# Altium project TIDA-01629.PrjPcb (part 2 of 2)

## Sheet TIDA-01629_Encoder.SchDoc
size 431 x 279 mm; Date: Not shown in title block; ApprovedBy: Not shown in title block; CheckedBy: Not shown in title block; Author: Not shown in title block; CompanyName: Not shown in title block; Engineer: Not shown in title block; Organization: Not shown in title block; Address1: Not shown in title block; Address2: Not shown in title block; Address3: Not shown in title block; Address4: Not shown in title block; DocumentNumber: 1; Revision: Use project parameter SCH_Rev; SheetNumber: 2; SheetTotal: 3; PageSetup: Record=PageOptions¦CenterHorizontal=True¦CenterVertical=True¦PrintScale=1.00¦XCorrection=1.00¦YCorrection=1.00¦PrintKind=0¦BorderSize=5000000¦LeftOffset=0¦BottomOffset=0¦Orientation=2¦PaperLength=1000¦PaperWidth=1000¦Scale=100¦PaperSource=15¦PrintQuality=600¦MediaType=1¦DitherType=10¦PaperKind=Letter¦PrintScaleMode=1
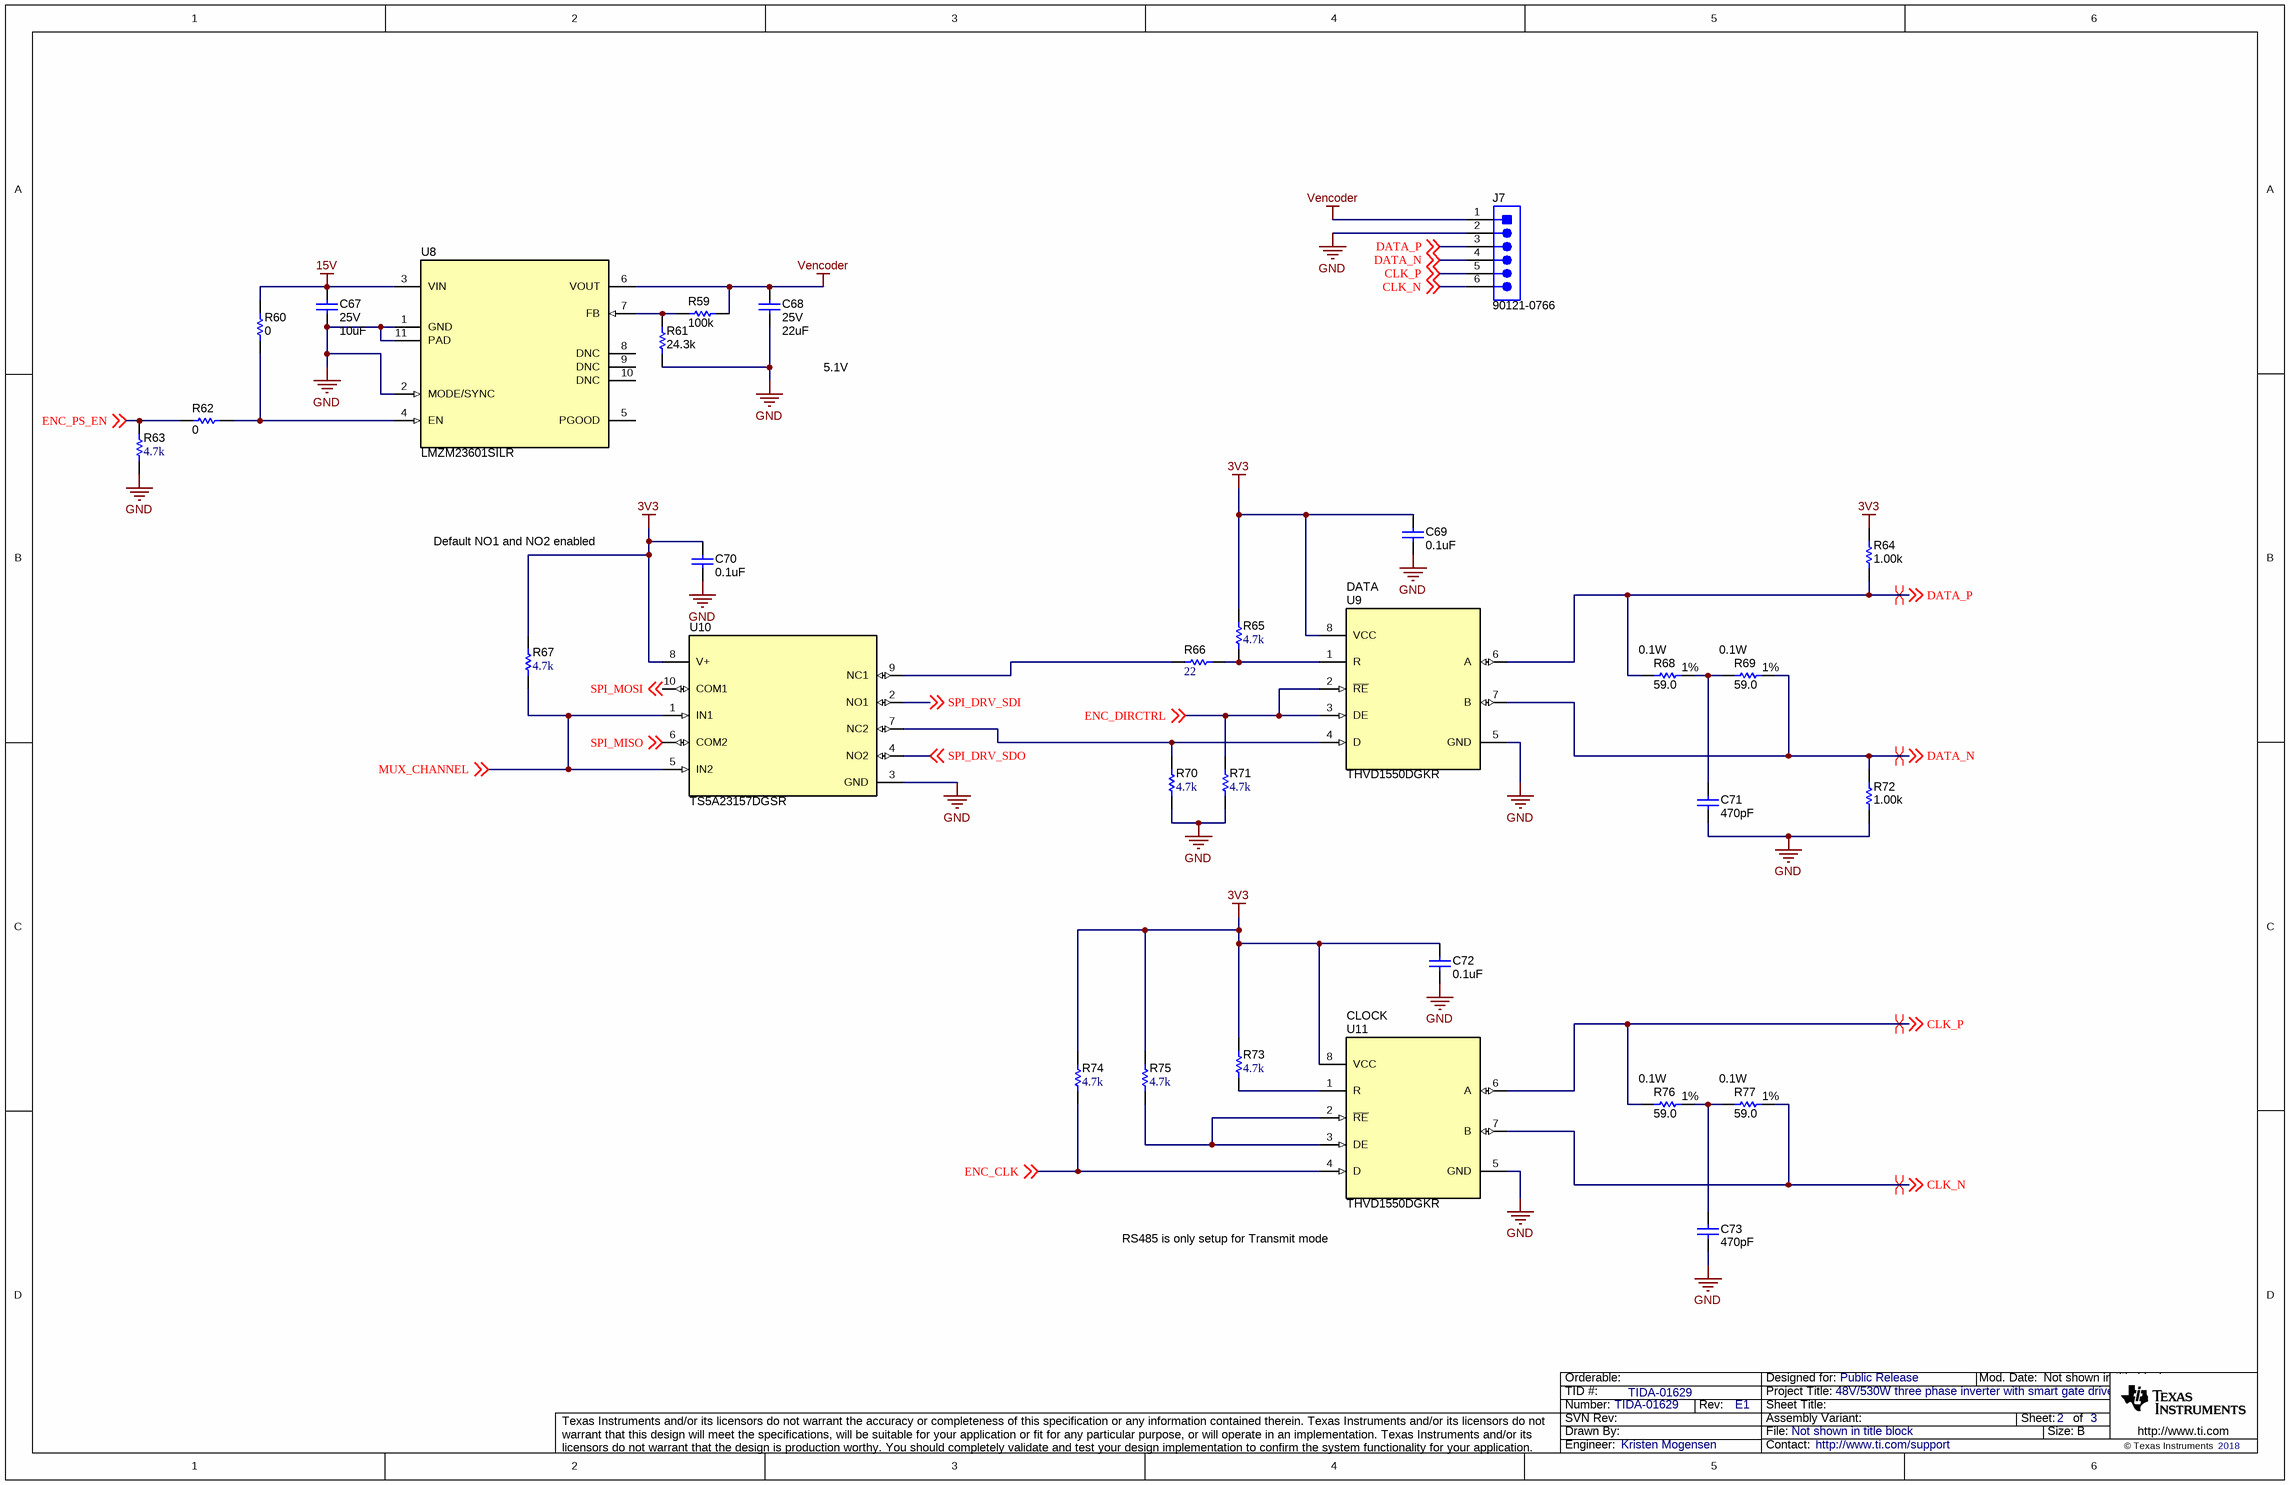
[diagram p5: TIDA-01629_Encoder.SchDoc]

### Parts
C67  VDC_V: 25V  ValueDisplayed: 10uF  [0805_HV]  (hidden comment: GRM21BZ71E106KE15L)
C68  VDC_V: 25V  ValueDisplayed: 22uF  [1210_270]  (hidden comment: GRM32ER71E226KE15L)
C69  ValueDisplayed: 0.1uF  [0402S]  (hidden comment: Capacitor)
C70  ValueDisplayed: 0.1uF  [0402S]  (hidden comment: Capacitor)
C71  ValueDisplayed: 470pF  [0603S]  (hidden comment: Capacitor)
C72  ValueDisplayed: 0.1uF  [0402S]  (hidden comment: Capacitor)
C73  ValueDisplayed: 470pF  [0603S]  (hidden comment: Capacitor)
J7  90121-0766  [Molex_90121-0766]
R59  ValueDisplayed: 100k  [0402]  (hidden comment: CRCW0402100KFKED)
R60  ValueDisplayed: 0  [0402S]  (hidden comment: Resistor)
R61  ValueDisplayed: 24.3k  [0402]  (hidden comment: CRCW040224K3FKED)
R62  ValueDisplayed: 0  [0402S]  (hidden comment: Resistor)
R63  ValueDisplayed: 4.7k  [0402S]  (hidden comment: CRCW04024K70JNED)
R64  ValueDisplayed: 1.00k  [0603L]  (hidden comment: CRCW06031K00FKEA)
R65  ValueDisplayed: 4.7k  [0402S]  (hidden comment: CRCW04024K70JNED)
R66  ValueDisplayed: 22  [0402S]  (hidden comment: CRCW040222R0JNED)
R67  ValueDisplayed: 4.7k  [0402S]  (hidden comment: CRCW04024K70JNED)
R68  ValueDisplayed: 59.0  Value1: 1%  Value2: 0.1W  [0603S]  (hidden comment: Resistor)
R69  ValueDisplayed: 59.0  Value1: 1%  Value2: 0.1W  [0603S]  (hidden comment: Resistor)
R70  ValueDisplayed: 4.7k  [0402S]  (hidden comment: CRCW04024K70JNED)
R71  ValueDisplayed: 4.7k  [0402S]  (hidden comment: CRCW04024K70JNED)
R72  ValueDisplayed: 1.00k  [0603L]  (hidden comment: CRCW06031K00FKEA)
R73  ValueDisplayed: 4.7k  [0402S]  (hidden comment: CRCW04024K70JNED)
R74  ValueDisplayed: 4.7k  [0402S]  (hidden comment: CRCW04024K70JNED)
R75  ValueDisplayed: 4.7k  [0402S]  (hidden comment: CRCW04024K70JNED)
R76  ValueDisplayed: 59.0  Value1: 1%  Value2: 0.1W  [0603S]  (hidden comment: Resistor)
R77  ValueDisplayed: 59.0  Value1: 1%  Value2: 0.1W  [0603S]  (hidden comment: Resistor)
U8  LMZM23601SILR  [SIL0010A]
U9  THVD1550DGKR  [DGK0008A_N]
U10  TS5A23157DGSR  [DGS0010A_L]
U11  THVD1550DGKR  [DGK0008A_N]

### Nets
3V3: C69.1 C70.1 C72.1 R64.2 R65.2 R67.2 R73.2 R74.2 R75.2 U9.8(VCC) U10.8(V+) U11.8(VCC)
15V: C67.1 R60.2 U8.3(VIN)
GND: C67.2 C68.2 C69.2 C70.2 C71.2 C72.2 C73.2 J7.2 R61.1 R63.1 R70.1 R71.1 R72.1 U8.1(GND) U8.2(MODE/SYNC) U8.11(PAD) U9.5(GND) U10.3(GND) U11.5(GND)
Vencoder: C68.1 J7.1 R59.1 U8.6(VOUT)
CLK_N: J7.6 R77.2 U11.7(B) ; off-sheet CLK_N
CLK_P: J7.5 R76.1 U11.6(A) ; off-sheet CLK_P
DATA_N: J7.4 R69.2 R72.2 U9.7(B) ; off-sheet DATA_N
DATA_P: J7.3 R64.1 R68.1 U9.6(A) ; off-sheet DATA_P
ENC_CLK: R74.1 U11.4(D) ; off-sheet ENC_CLK
ENC_DIRCTRL: R71.2 U9.2(~{RE}) U9.3(DE) ; off-sheet ENC_DIRCTRL
ENC_PS_EN: R62.2 R63.2 ; off-sheet ENC_PS_EN
MUX_CHANNEL: R67.1 U10.1(IN1) U10.5(IN2) ; off-sheet MUX_CHANNEL
SPI_DRV_SDI: U10.2(NO1) ; off-sheet SPI_DRV_SDI
SPI_DRV_SDO: U10.4(NO2) ; off-sheet SPI_DRV_SDO
SPI_MISO: U10.6(COM2) ; off-sheet SPI_MISO
SPI_MOSI: U10.10(COM1) ; off-sheet SPI_MOSI
NetC71_1: C71.1 R68.2 R69.1
NetC73_1: C73.1 R76.2 R77.1
NetR59_2: R59.2 R61.2 U8.7(FB)
NetR60_1: R60.1 R62.1 U8.4(EN)
NetR65_1: R65.1 R66.2 U9.1(R)
NetR66_1: R66.1 U10.9(NC1)
NetR70_2: R70.2 U9.4(D) U10.7(NC2)
NetR73_1: R73.1 U11.1(R)
NetR75_1: R75.1 U11.2(~{RE}) U11.3(DE)

Not connected (* = marked no-connect by the designer): U8 5(PGOOD) 8(DNC) 9(DNC) 10(DNC)

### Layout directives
differential pair: CLK_N, CLK_P, DATA_N, DATA_P

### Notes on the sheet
- 5.1V
- Default NO1 and NO2 enabled
- DATA
- (near U11) CLOCK
- RS485 is only setup for Transmit mode

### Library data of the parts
C67 = CMP-0008378-2: CAP, CERM, 10 uF, 25 V, +/- 10%, X7R, 0805; Manufacturer: MuRata; TaMin_C: -55°C; Polarized: N; SizeAreaWB_mm2: 6.75; Value1: Unknown; U/M: EA; Value: 10uF; TaMax_C: 125°C; SizeZ_mm: 1.45; SizeX_mm: 2; SizeY_mm: 1.25; Cap_Case: 0805; SizeArea_mm2: 2.5; Cap_F: 10µF; AEC Category: Q200
C68 = CMP-0009224-2: CAP, CERM, 22 uF, 25 V, +/- 10%, X7R, 1210; Manufacturer: MuRata; TaMin_C: -55°C; Polarized: N; SizeAreaWB_mm2: 14.7; Value1: Unknown; U/M: EA; Value: 22uF; TaMax_C: 125°C; SizeZ_mm: 2.7; SizeX_mm: 3.2; SizeY_mm: 2.5; Cap_Case: 1210; SizeArea_mm2: 8; Cap_F: 22µF; AEC Category: Q200
C69 C70 C72 = CMP-0006228-2: CAP, CERM, 0.1 uF, 16 V, +/- 10%, X7R, 0402; PartNumber: 885012205037; Manufacturer: Wurth Elektronik; Polarized: N; Value: 0.1uF; U/M: EA; Cap_F: 100nF; Value1: Unknown; VDC_V: 16V; TaMin_C: -55°C; TaMax_C: 125°C; Cap_Case: 0402; SizeArea_mm2: 0.5; SizeAreaWB_mm2: 3; SizeX_mm: 1; SizeZ_mm: 0.6; AEC Category: Q200
C71 C73 = CMP-0006834-5: CAP, CERM, 470 pF, 50 V, +/- 10%, X7R, 0603; PartNumber: 885012206081; Manufacturer: Wurth Elektronik; Polarized: N; Value: 470pF; U/M: EA; Value1: Unknown; VDC_V: 50V; TaMin_C: -55°C; TaMax_C: 125°C; Cap_Case: 0603; SizeArea_mm2: 1.28; SizeAreaWB_mm2: 4.68; SizeX_mm: 1.6; SizeY_mm: 0.8; SizeZ_mm: 1; AEC Category: Q200
J7 = CMP-0055334-1: Header, 2.54mm, 6x1, Gold, R/A, TH; Manufacturer: Molex; CNHeader: TRUE; Current_A: 3A; Shrouded: N; Gender: Male; Voltage_V: 350V; Row_Count: 1; Pitch_mm: 2.54; CT: FALSE; Cert_UL: Y
R59 = CMP-0025950-3: RES, 100 k, 1%, 0.063 W, AEC-Q200 Grade 0, 0402; Manufacturer: Vishay-Dale; Power_W: 63mW; TempCo: 100 ppm/C; Value: 100k; EIA_Code: E96; SizeX_mm: 1; SizeY_mm: 0.5; SizeZ_mm: 0.6; Value2: 0.063W; AEC Qualified: Y; VDC_V: 50V; AEC Category: Q200; AEC Grade: 0
R60 R62 = CMP-0026822-3: RES, 0, 5%, 0.063 W, AEC-Q200 Grade 0, 0402; PartNumber: CRCW04020000Z0ED; Manufacturer: Vishay-Dale; Value: 0; Value_Code: 0000; Power_W: 63mW; Value2: 0.063W; VDC_V: 50V; TempCo: 200 ppm/C; SizeArea_mm2: 0.5; SizeX_mm: 1; SizeZ_mm: 0.6; EIA_Code: E24; AEC Category: Q200; AEC Qualified: Y
R61 = CMP-0026195-2: RES, 24.3 k, 1%, 0.063 W, AEC-Q200 Grade 0, 0402; Manufacturer: Vishay-Dale; Power_W: 63mW; TempCo: 100 ppm/C; Value_Code: 24k3; Value: 24.3k; EIA_Code: E96; SizeX_mm: 1; SizeY_mm: 0.5; SizeZ_mm: 0.6; Value2: 0.063W; AEC Qualified: Y; VDC_V: 50V; AEC Category: Q200; AEC Grade: 0
R63 R65 R67 R70 R71 R73-R75 = CMP-0026938-4: RES, 4.7 k, 5%, 0.063 W, 0402; Manufacturer: Vishay-Dale; Power_W: 63mW; TempCo: 200 ppm/C; Value_Code: 4k70; U/M: EA; Value: 4.7k; EIA_Code: E24; SizeX_mm: 1; SizeY_mm: 0.5; SizeZ_mm: 0.6; Value2: 0.063W; CompType: Resistor; VDC_V: 50V; AEC Category: Q200
R64 R72 = CMP-0022109-5: RES, 1.00 k, 1%, 0.1 W, AEC-Q200 Grade 0, 0603; Manufacturer: Vishay-Dale; Power_W: 100mW; TempCo: 100 ppm/C; Value_Code: 1k00; Value: 1.00k; EIA_Code: E96; Res_ohm: 1k; SizeX_mm: 1.6; SizeY_mm: 0.8; SizeZ_mm: 1; Value2: 0.1W; SizeArea_mm2: 1.28; AEC Qualified: Y; VDC_V: 75V; AEC Category: Q200; AEC Grade: 0
R66 = CMP-0026880-2: RES, 22, 5%, 0.063 W, 0402; Manufacturer: Vishay-Dale; Power_W: 63mW; TempCo: 200 ppm/C; Value_Code: 22R0; U/M: EA; Value: 22; EIA_Code: E24; SizeX_mm: 1; SizeY_mm: 0.5; SizeZ_mm: 0.6; Value2: 0.063W; CompType: Resistor; VDC_V: 50V; AEC Category: Q200
R68 R69 R76 R77 = CMP-0023196-3: RES, 59.0, 1%, 0.1 W, 0603; PartNumber: RC0603FR-0759RL; Manufacturer: Yageo America; Value: 59.0; Res_ohm: 59; Value_Code: 59R0; Power_W: 100mW; VDC_V: 150V; TempCo: 200 ppm/C; SizeArea_mm2: 1.28; SizeX_mm: 1.6; SizeY_mm: 0.8; SizeZ_mm: 1; EIA_Code: E96; U/M: EA; AEC Category: Q200
U8 = CMP-0065261-5: 36-V 1-A Step-Down DC-DC Nano Module, SIL0010A (uSIP-10); Manufacturer: Texas Instruments; Alternate PartNumber: LMZM23601SILT; SizeX_mm: 3.8; SizeY_mm: 3.0; CompType: IC; SizeZ_mm: 1.615; SizeArea_mm2: 11.4; SizeAreaWB_mm2: 19.2; AEC Category: Q200; AEC Qualified: N
U9 U11 = CMP-0074780-2: 5-V RS-485 Transceivers With +/-16-kV IEC ESD Protection, DGK0008A (VSSOP-8); Manufacturer: Texas Instruments; SizeX_mm: 5.05; SizeY_mm: 3.1; CompType: IC; SizeZ_mm: 1.1; SizeArea_mm2: 15.655; SizeAreaWB_mm2: 35.955; U/M: EA
U10 = CMP-0067418-1: DUAL 10-Ohm SPDT ANALOG SWITCH, DGS0010A (VSSOP-10); Alternate PartNumber: TS5A23157DGST; Alternate Manufacturer: Texas Instruments; Green_Lifecycle: Active; SizeAreaWB_mm2: 23.6; Green_REACh: Passed; U/M: EA; SizeZ_mm: 1.1; SizeX_mm: 4.9; SizeY_mm: 3.0; SizeArea_mm2: 14.7; CompType: IC

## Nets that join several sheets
3V3: TIDA-01629_Gate_Driver (7 pins), TIDA-01629_Interface (D5.3 D6.3 R45.1), TIDA-01629_Encoder (12 pins)
3V3_Analog: TIDA-01629_CurrentSense (9 pins), TIDA-01629_Gate_Driver (C56.1 L4.2)
15V: TIDA-01629_Gate_Driver (J1.1 L6.1 R37.2), TIDA-01629_Encoder (C67.1 R60.2 U8.3)
GND: TIDA-01629_CurrentSense (25 pins), TIDA-01629_Gate_Driver (72 pins), TIDA-01629_Interface (12 pins), TIDA-01629_Encoder (19 pins)
Vin: TIDA-01629_CurrentSense (R1.1), TIDA-01629_Gate_Driver (35 pins), TIDA-01629_Interface (J5.1 R58.2)
EN_DRV: TIDA-01629_Gate_Driver (U6.33), TIDA-01629_Interface (R57.2)
ENC_CLK: TIDA-01629_Interface (J3.13), TIDA-01629_Encoder (R74.1 U11.4)
ENC_DIRCTRL: TIDA-01629_Interface (J3.20), TIDA-01629_Encoder (R71.2 U9.2 U9.3)
ENC_PS_EN: TIDA-01629_Interface (J2.15), TIDA-01629_Encoder (R62.2 R63.2)
I_A: TIDA-01629_CurrentSense (U1.8), TIDA-01629_Interface (R53.2)
I_B: TIDA-01629_CurrentSense (U2.8), TIDA-01629_Interface (R52.2)
I_C: TIDA-01629_CurrentSense (U3.8), TIDA-01629_Interface (R51.2)
MUX_CHANNEL: TIDA-01629_Interface (J3.8), TIDA-01629_Encoder (R67.1 U10.1 U10.5)
nFault: TIDA-01629_Gate_Driver (R35.1 U6.28), TIDA-01629_Interface (J2.9)
PH_A_N: TIDA-01629_CurrentSense (R2.1 U1.3), TIDA-01629_Gate_Driver (13 pins)
PH_A_P: TIDA-01629_CurrentSense (R2.2 R3.1 U1.2), TIDA-01629_Interface (J6.1)
PH_B_N: TIDA-01629_CurrentSense (R7.1 U2.3), TIDA-01629_Gate_Driver (13 pins)
PH_B_P: TIDA-01629_CurrentSense (R7.2 R8.1 U2.2), TIDA-01629_Interface (J6.2)
PH_C_N: TIDA-01629_CurrentSense (R11.1 U3.3), TIDA-01629_Gate_Driver (13 pins)
PH_C_P: TIDA-01629_CurrentSense (R11.2 R12.1 U3.2), TIDA-01629_Interface (J6.3)
PWM_AH: TIDA-01629_Gate_Driver (R24.1), TIDA-01629_Interface (J3.11)
PWM_AL: TIDA-01629_Gate_Driver (R25.1), TIDA-01629_Interface (J3.9)
PWM_BH: TIDA-01629_Gate_Driver (R26.1), TIDA-01629_Interface (J3.7)
PWM_BL: TIDA-01629_Gate_Driver (R27.1), TIDA-01629_Interface (J3.5)
PWM_CH: TIDA-01629_Gate_Driver (R28.1), TIDA-01629_Interface (J3.3)
PWM_CL: TIDA-01629_Gate_Driver (R29.1), TIDA-01629_Interface (J3.1)
SPI_CLK: TIDA-01629_Gate_Driver (R34.2 U6.31), TIDA-01629_Interface (J3.15 R50.1)
SPI_CS: TIDA-01629_Gate_Driver (U6.32), TIDA-01629_Interface (J3.18)
SPI_DRV_SDI: TIDA-01629_Gate_Driver (U6.30), TIDA-01629_Encoder (U10.2)
SPI_DRV_SDO: TIDA-01629_Gate_Driver (R30.1 R31.1), TIDA-01629_Encoder (U10.4)
SPI_MISO: TIDA-01629_Interface (J3.14), TIDA-01629_Encoder (U10.6)
SPI_MOSI: TIDA-01629_Interface (R56.2), TIDA-01629_Encoder (U10.10)
Temp: TIDA-01629_CurrentSense (U5.3), TIDA-01629_Interface (J4.3)
V_A: TIDA-01629_CurrentSense (C4.1 R3.2 R6.2), TIDA-01629_Interface (R48.2)
V_B: TIDA-01629_CurrentSense (C7.1 R8.2 R10.2), TIDA-01629_Interface (R47.2)
V_C: TIDA-01629_CurrentSense (C10.1 R12.2 R17.2), TIDA-01629_Interface (R46.2)
V_Gate_driver: TIDA-01629_Gate_Driver (C13.2 R19.1 R21.2), TIDA-01629_Interface (J4.1)
Vbus: TIDA-01629_CurrentSense (C2.1 R1.2 R4.2), TIDA-01629_Interface (R49.2)

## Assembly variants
001: not fitted C67 C68 C69 C71 C72 C73 J7 R59 R60 R61 R62 R63 R64 R65 R66 R67 R68 R69 R70 R71 R72 R73 R74 R75 R76 R77 U8 U9 U11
